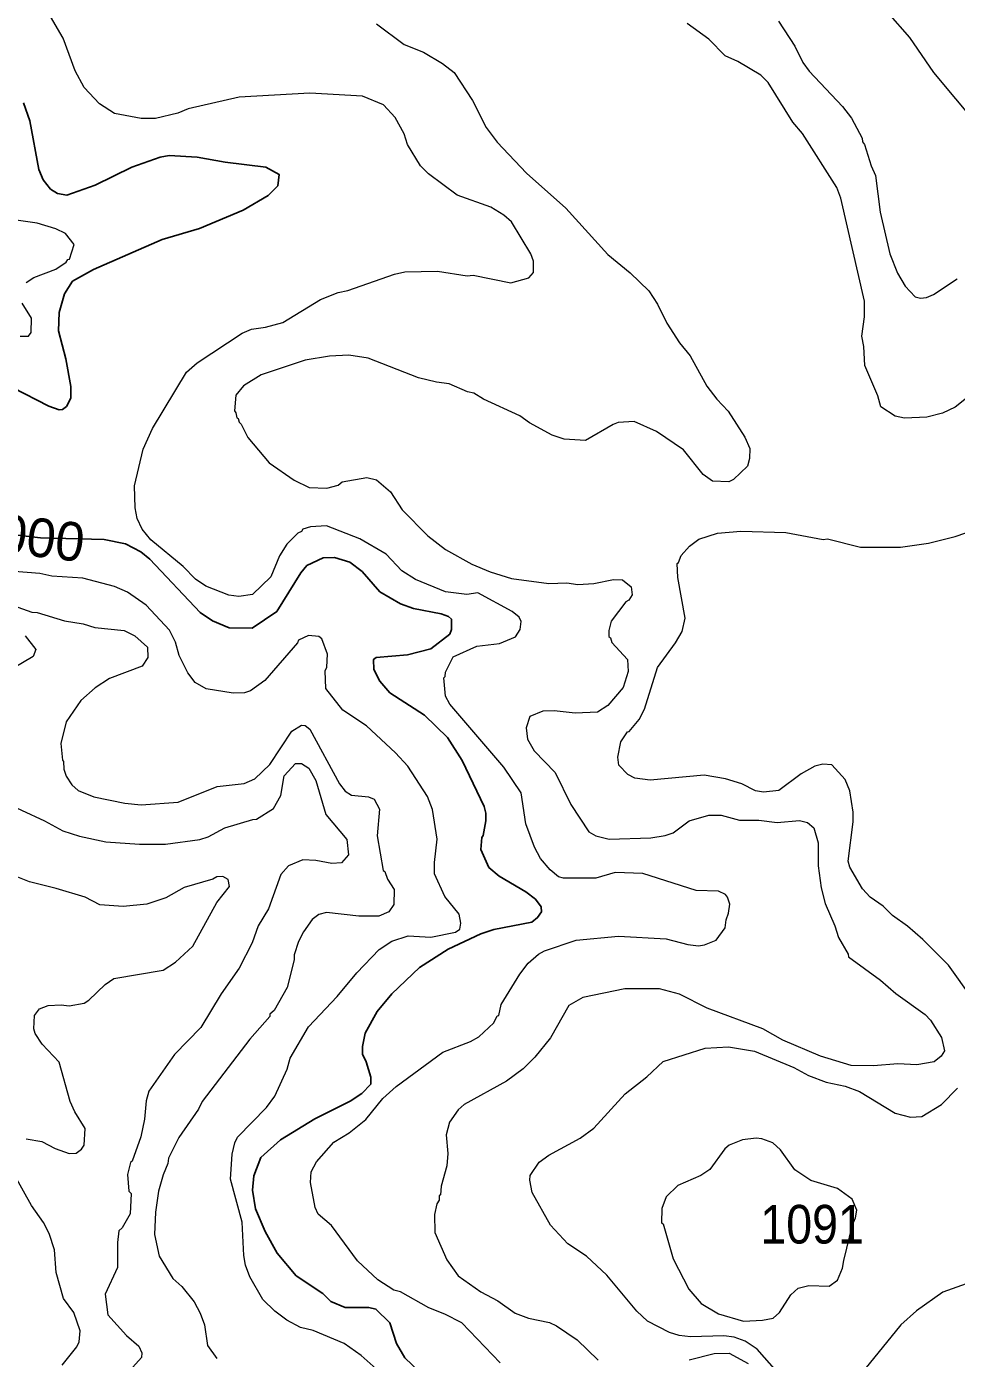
# Model space of a CAD drawing. Extents: x 447.8 to 473.9, y 7733.1 to 7760.8.
# Drawn here: x 462.61 to 464.533, y 7750.473 to 7753.226 of the extents above; entities that cross this region are included whole.
import ezdxf
from ezdxf.enums import TextEntityAlignment as Align

# ---------------------------------------------------------------- set-up
doc = ezdxf.new("R2010")
doc.units = 0
doc.header["$LTSCALE"] = 0.032
doc.layers.add('1', color=7, linetype='Continuous', lineweight=25)
doc.layers.add('2', color=7, linetype='Continuous', lineweight=13)
doc.layers.add('21', color=7, linetype='Continuous')
doc.layers.add('61', color=7, linetype='Continuous')

msp = doc.modelspace()

# ---------------------------------------------------------------- linework, layer by layer
at = {"layer": '1'}
for points in [[(462.5811, 7752.4805), (462.6558, 7752.4414), (462.6776, 7752.434), (462.6846, 7752.4344), (462.6928, 7752.4412), (462.7014, 7752.4584), (462.7016, 7752.482), (462.6913, 7752.5394), (462.676, 7752.5971), (462.6776, 7752.6356), (462.6887, 7752.674), (462.705, 7752.7), (462.7486, 7752.7239), (462.8905, 7752.7865), (462.9676, 7752.8088), (463.0578, 7752.8468), (463.1094, 7752.8769), (463.1295, 7752.8973), (463.1324, 7752.9208), (463.1048, 7752.9356), (463.0206, 7752.9461), (462.9626, 7752.9566), (462.9049, 7752.9597), (462.886, 7752.9565), (462.828, 7752.9355), (462.7521, 7752.8984), (462.6936, 7752.878), (462.6739, 7752.8814), (462.6596, 7752.8904), (462.6442, 7752.9094), (462.6354, 7752.9308), (462.6167, 7753.0315), (462.6037, 7753.069)], [(463.5601, 7751.6002), (463.5562, 7751.6143), (463.5106, 7751.7089), (463.4805, 7751.7568), (463.4329, 7751.8027), (463.3611, 7751.849), (463.3405, 7751.8733), (463.3285, 7751.8969), (463.3277, 7751.9181), (463.3327, 7751.9217), (463.3978, 7751.9274), (463.4458, 7751.9399), (463.4853, 7751.9704), (463.4888, 7751.98), (463.4887, 7752.001), (463.4823, 7752.0066), (463.4671, 7752.012), (463.4099, 7752.0231), (463.3835, 7752.0333), (463.3408, 7752.0579), (463.3043, 7752.0997), (463.2784, 7752.119), (463.2467, 7752.1285), (463.2234, 7752.1278), (463.1897, 7752.1122), (463.1772, 7752.0971), (463.1275, 7752.0171), (463.0766, 7751.9828), (463.0293, 7751.9834), (462.9944, 7751.9977), (462.9688, 7752.0152), (462.8653, 7752.1251), (462.8464, 7752.1407), (462.8148, 7752.1569), (462.7705, 7752.1661), (462.6392, 7752.1696), (462.5912, 7752.1752)], [(463.566, 7751.4879), (463.5498, 7751.5249), (463.5512, 7751.5501), (463.5544, 7751.554), (463.5601, 7751.5843), (463.5601, 7751.6002)], [(463.4227, 7750.4453), (463.3923, 7750.4742), (463.3751, 7750.5035), (463.3613, 7750.5468), (463.3324, 7750.575), (463.318, 7750.5781), (463.2691, 7750.5783), (463.2396, 7750.5903), (463.2226, 7750.6071), (463.1679, 7750.6434), (463.1285, 7750.6905), (463.1037, 7750.7352), (463.0837, 7750.7824), (463.0776, 7750.8208), (463.0802, 7750.8507), (463.0945, 7750.8883), (463.1353, 7750.9245), (463.2065, 7750.9685), (463.279, 7751.0048), (463.3034, 7751.0204), (463.322, 7751.0402), (463.3218, 7751.0543), (463.3123, 7751.0859), (463.3045, 7751.102), (463.3045, 7751.118), (463.3105, 7751.1452), (463.335, 7751.1901), (463.3651, 7751.2265), (463.4225, 7751.2808), (463.4818, 7751.3191), (463.5496, 7751.3504), (463.5762, 7751.3595), (463.6552, 7751.375), (463.6669, 7751.3842), (463.6746, 7751.3965), (463.6745, 7751.4064), (463.6625, 7751.4226), (463.6425, 7751.4377), (463.5871, 7751.4698), (463.566, 7751.4879)]]:
    msp.add_lwpolyline(points, dxfattribs=at)
at = {"layer": '2'}
for points in [[(464.6192, 7752.9723), (464.4864, 7753.1315), (464.4364, 7753.204), (464.392, 7753.255), (464.3576, 7753.3119), (464.3206, 7753.3917), (464.3077, 7753.4247), (464.2879, 7753.4731), (464.2343, 7753.6308), (464.2332, 7753.6641), (464.2311, 7753.6666), (464.2347, 7753.6953), (464.2547, 7753.7318), (464.2762, 7753.7542), (464.3421, 7753.7868), (464.3901, 7753.8066), (464.4936, 7753.8318), (464.5449, 7753.8494)], [(463.2746, 7752.6809), (463.3708, 7752.7146), (463.3926, 7752.7192), (463.4599, 7752.7208), (463.5212, 7752.7108), (463.5339, 7752.7127), (463.6112, 7752.6969), (463.6489, 7752.7072), (463.6586, 7752.7178), (463.6586, 7752.7411), (463.6528, 7752.7567), (463.6131, 7752.8224), (463.5968, 7752.8365), (463.5702, 7752.8533), (463.5007, 7752.8776), (463.4415, 7752.922), (463.425, 7752.9387), (463.3981, 7752.9824), (463.391, 7753.0046), (463.3725, 7753.0383), (463.3485, 7753.0646), (463.3051, 7753.0828), (463.1959, 7753.0889), (463.0495, 7753.0807), (462.944, 7753.056), (462.9229, 7753.0475), (462.8764, 7753.036), (462.8469, 7753.036), (462.7921, 7753.0465), (462.7607, 7753.0667), (462.7294, 7753.1002), (462.7103, 7753.1347), (462.6855, 7753.2021), (462.6597, 7753.247)], [(463.3339, 7753.2318), (463.3908, 7753.1892), (463.431, 7753.1737), (463.4702, 7753.1501), (463.4944, 7753.1313), (463.5322, 7753.0733), (463.5606, 7753.018), (463.583, 7752.9876), (463.644, 7752.9231), (463.725, 7752.851), (463.8121, 7752.7551), (463.8581, 7752.7171), (463.8966, 7752.6802), (463.9149, 7752.6526), (463.9338, 7752.6131), (463.9604, 7752.5723), (463.9827, 7752.5458), (464.0171, 7752.4831), (464.0376, 7752.4559), (464.0609, 7752.431), (464.0956, 7752.3778), (464.106, 7752.3542)], [(464.5541, 7752.4579), (464.5301, 7752.4397), (464.5041, 7752.427), (464.4719, 7752.4187), (464.4255, 7752.4171), (464.4064, 7752.4209), (464.3766, 7752.4403), (464.3704, 7752.463), (464.3436, 7752.5257), (464.3416, 7752.5653), (464.3376, 7752.5863), (464.3426, 7752.6264), (464.3432, 7752.6587), (464.2943, 7752.8715), (464.2855, 7752.894), (464.2149, 7753.0052), (464.1945, 7753.0285), (464.1434, 7753.1107), (464.1283, 7753.1256), (464.0808, 7753.1539), (464.0548, 7753.1658), (464.0213, 7753.2), (463.9763, 7753.2324)], [(464.1651, 7753.2373), (464.199, 7753.1858), (464.2157, 7753.1524), (464.2282, 7753.1339), (464.2974, 7753.061), (464.3158, 7753.0369), (464.3383, 7752.9955), (464.3387, 7752.9884), (464.3432, 7752.9829), (464.3566, 7752.9383), (464.3657, 7752.9185), (464.3754, 7752.8424), (464.3953, 7752.7568)], [(462.6089, 7752.697), (462.6253, 7752.7074), (462.6706, 7752.7245), (462.6918, 7752.7393), (462.6951, 7752.7447), (462.6985, 7752.7453), (462.7087, 7752.7756), (462.6905, 7752.7986), (462.6708, 7752.8085), (462.6318, 7752.8201), (462.5791, 7752.8276)], [(464.3953, 7752.7568), (464.4113, 7752.7163), (464.4268, 7752.6894), (464.4475, 7752.6676), (464.4584, 7752.6648), (464.4711, 7752.6663)], [(463.0752, 7752.6006), (463.104, 7752.6046), (463.1398, 7752.6143), (463.2177, 7752.6618), (463.2547, 7752.6767), (463.2746, 7752.6809)], [(464.4711, 7752.6663), (464.4857, 7752.6727), (464.5346, 7752.7046)], [(462.5971, 7752.5863), (462.6142, 7752.5864), (462.6198, 7752.5942), (462.6199, 7752.6235), (462.601, 7752.6544)], [(463.3368, 7750.6357), (463.2941, 7750.6744), (463.2407, 7750.7478), (463.2129, 7750.771), (463.2071, 7750.7847), (463.1971, 7750.8368), (463.1985, 7750.8589), (463.2095, 7750.8794), (463.2454, 7750.9199), (463.2774, 7750.9392), (463.3119, 7750.9666), (463.3467, 7751.01), (463.3747, 7751.0348), (463.4712, 7751.1064), (463.5279, 7751.1284), (463.5452, 7751.138), (463.5767, 7751.1664), (463.5834, 7751.1815), (463.5865, 7751.1821), (463.5918, 7751.2047), (463.63, 7751.2671), (463.6473, 7751.2898), (463.6689, 7751.3085), (463.6814, 7751.3153), (463.7465, 7751.3373), (463.8343, 7751.3461), (463.9328, 7751.3405), (463.9774, 7751.3286), (463.9999, 7751.3262), (464.0117, 7751.3278), (464.0361, 7751.3375), (464.0546, 7751.3629), (464.0565, 7751.3796), (464.0619, 7751.3935), (464.0642, 7751.412), (464.0596, 7751.4268), (464.0552, 7751.432), (464.0411, 7751.4392), (463.9946, 7751.44), (463.8845, 7751.4754), (463.8271, 7751.4776), (463.7875, 7751.4655), (463.7206, 7751.4658), (463.7104, 7751.4685), (463.6926, 7751.4832), (463.6728, 7751.5066), (463.6602, 7751.53), (463.6424, 7751.5783), (463.6328, 7751.6421), (463.5968, 7751.6951), (463.4852, 7751.8253), (463.4764, 7751.8423), (463.4728, 7751.8797), (463.4759, 7751.8827), (463.4767, 7751.8918), (463.4926, 7751.9236), (463.5409, 7751.9457), (463.5881, 7751.9512), (463.6215, 7751.9649), (463.6311, 7751.9801), (463.633, 7751.9967), (463.6289, 7752.0056), (463.6144, 7752.0172), (463.5431, 7752.0554), (463.5205, 7752.0524), (463.4763, 7752.0579), (463.4146, 7752.0832), (463.3864, 7752.1012), (463.3536, 7752.1355), (463.299, 7752.1672), (463.2304, 7752.1942), (463.1974, 7752.1919), (463.1813, 7752.187), (463.1786, 7752.1824), (463.1707, 7752.179), (463.1484, 7752.156), (463.1334, 7752.1324), (463.115, 7752.089), (463.0772, 7752.052), (463.049, 7752.0484), (463.0284, 7752.0508), (462.9809, 7752.0698), (462.9595, 7752.0839), (462.9338, 7752.1102), (462.867, 7752.1651), (462.8489, 7752.1874), (462.8389, 7752.2091), (462.8348, 7752.2312), (462.8333, 7752.2771), (462.851, 7752.3528), (462.8706, 7752.3953), (462.9405, 7752.5122), (462.9629, 7752.5309), (463.0562, 7752.5927), (463.0752, 7752.6006)], [(464.0288, 7752.2865), (464.0096, 7752.3003), (463.9683, 7752.351), (463.9125, 7752.3892), (463.8665, 7752.4102), (463.8338, 7752.4075), (463.8229, 7752.4037), (463.7658, 7752.3705), (463.7219, 7752.3736), (463.6973, 7752.3818), (463.6498, 7752.4072), (463.6298, 7752.4218), (463.5552, 7752.456), (463.5352, 7752.4683), (463.5218, 7752.471), (463.4837, 7752.4877), (463.4576, 7752.491), (463.4205, 7752.5002), (463.3162, 7752.5407), (463.2762, 7752.5469), (463.2364, 7752.5453), (463.1862, 7752.5366), (463.0954, 7752.5065), (463.0589, 7752.4834), (463.0427, 7752.4641), (463.0399, 7752.4318), (463.0431, 7752.428), (463.0447, 7752.4174), (463.0478, 7752.4161), (463.0495, 7752.4085), (463.0541, 7752.4044), (463.0678, 7752.3765), (463.1118, 7752.3245), (463.1633, 7752.2884), (463.1947, 7752.2737), (463.231, 7752.2719), (463.2547, 7752.2786), (463.2624, 7752.2851), (463.314, 7752.2944), (463.3335, 7752.2895), (463.3627, 7752.2642), (463.3871, 7752.2275), (463.4402, 7752.1738), (463.4761, 7752.145), (463.5307, 7752.1147), (463.5686, 7752.099), (463.613, 7752.085), (463.6901, 7752.0749), (463.7272, 7752.0764), (463.7498, 7752.0732), (463.7834, 7752.0753), (463.8235, 7752.0836), (463.8425, 7752.0829), (463.8607, 7752.068), (463.8623, 7752.0519), (463.8556, 7752.0402), (463.8496, 7752.037), (463.8193, 7751.9972), (463.8142, 7751.9776), (463.8143, 7751.9652), (463.8174, 7751.963), (463.8204, 7751.9527), (463.8529, 7751.9177), (463.8543, 7751.8933), (463.844, 7751.8601), (463.8124, 7751.8229), (463.7908, 7751.8089), (463.7446, 7751.8071), (463.7008, 7751.8118), (463.678, 7751.811), (463.6508, 7751.7998), (463.6432, 7751.7768), (463.6458, 7751.7532), (463.6601, 7751.7288), (463.7035, 7751.6845), (463.7356, 7751.618), (463.7727, 7751.5619), (463.7876, 7751.5534), (463.8147, 7751.5466), (463.9012, 7751.549), (463.9306, 7751.5539), (463.9475, 7751.5598), (463.9804, 7751.5843), (464.021, 7751.5962), (464.0467, 7751.5962), (464.0844, 7751.5859), (464.1243, 7751.5858), (464.1621, 7751.581), (464.2086, 7751.585), (464.2248, 7751.5808), (464.2384, 7751.5699), (464.2472, 7751.539), (464.2473, 7751.4916), (464.2536, 7751.446), (464.2613, 7751.4134)], [(464.106, 7752.3542), (464.1053, 7752.3336), (464.1012, 7752.3173), (464.0722, 7752.2901), (464.0621, 7752.2851), (464.0288, 7752.2865)], [(464.1337, 7751.6436), (464.1173, 7751.6465), (464.0894, 7751.6606), (464.0552, 7751.6712), (464.0111, 7751.6789), (463.8996, 7751.6684), (463.8682, 7751.6722), (463.8536, 7751.68), (463.8349, 7751.6995), (463.8327, 7751.7162), (463.8391, 7751.7477), (463.8525, 7751.7682), (463.8565, 7751.7693), (463.8769, 7751.7937), (463.8879, 7751.815), (463.9149, 7751.901), (463.9523, 7751.9524), (463.9657, 7751.9755), (463.9721, 7752.0034), (463.957, 7752.0873), (463.9554, 7752.1161), (463.9585, 7752.1183), (463.9638, 7752.1331), (463.9807, 7752.1523), (464.0003, 7752.1669), (464.0386, 7752.179), (464.0871, 7752.183), (464.1801, 7752.1806), (464.2577, 7752.1662), (464.2664, 7752.1675), (464.3346, 7752.1502), (464.4175, 7752.15), (464.4751, 7752.1582), (464.5305, 7752.1725), (464.5927, 7752.1932)], [(463.106, 7750.992), (463.1234, 7751.0154), (463.1488, 7751.0709), (463.1555, 7751.0939), (463.1928, 7751.1585), (463.2521, 7751.2209), (463.293, 7751.2698), (463.3395, 7751.318), (463.3656, 7751.3359), (463.399, 7751.3469), (463.4458, 7751.3437), (463.4972, 7751.3539), (463.5063, 7751.3607), (463.508, 7751.373), (463.5044, 7751.3917), (463.4748, 7751.4278), (463.4537, 7751.4746), (463.4536, 7751.4983), (463.459, 7751.5464), (463.4496, 7751.6079), (463.4395, 7751.6346), (463.3987, 7751.6974), (463.3728, 7751.7251), (463.3127, 7751.7804), (463.2638, 7751.8131), (463.2291, 7751.8579), (463.2274, 7751.8941), (463.2308, 7751.9022), (463.2323, 7751.9289), (463.2208, 7751.9604), (463.2147, 7751.9652), (463.1931, 7751.9673), (463.1726, 7751.958), (463.1703, 7751.952), (463.1026, 7751.8746), (463.0729, 7751.8532), (463.0607, 7751.8488), (463.0372, 7751.848), (462.9816, 7751.857), (462.9585, 7751.8701), (462.9434, 7751.8906), (462.9257, 7751.9261), (462.9177, 7751.9536), (462.9054, 7751.9783), (462.8571, 7752.0299), (462.8191, 7752.0573), (462.7919, 7752.0687), (462.7264, 7752.0859), (462.6626, 7752.0901), (462.6375, 7752.0956), (462.585, 7752.0998)], [(462.5452, 7752.0425), (462.6209, 7752.0156), (462.6318, 7752.0153), (462.6885, 7751.9979), (462.7273, 7751.9914), (462.7513, 7751.9839), (462.8122, 7751.9778), (462.8341, 7751.9669), (462.8603, 7751.9437), (462.8611, 7751.9217), (462.8494, 7751.9044), (462.7816, 7751.8783), (462.7516, 7751.8593), (462.7225, 7751.8334), (462.6919, 7751.7891), (462.6809, 7751.7445), (462.6841, 7751.7096), (462.6866, 7751.7068), (462.6874, 7751.691), (462.6917, 7751.6764), (462.7037, 7751.6591), (462.7167, 7751.6472), (462.7494, 7751.634), (462.8134, 7751.6209), (462.8471, 7751.6171), (462.9238, 7751.6226), (463.0041, 7751.6551), (463.0598, 7751.6613), (463.0819, 7751.6714), (463.1134, 7751.701), (463.1589, 7751.7697), (463.1785, 7751.7821), (463.1861, 7751.7812), (463.1955, 7751.7741), (463.2575, 7751.661), (463.2689, 7751.6454), (463.2819, 7751.6376), (463.3169, 7751.634), (463.329, 7751.629), (463.3396, 7751.6087), (463.335, 7751.553), (463.3476, 7751.4814), (463.351, 7751.4797), (463.3568, 7751.4636), (463.3701, 7751.4424), (463.3699, 7751.4117), (463.359, 7751.3961), (463.3383, 7751.3871), (463.2973, 7751.3871), (463.2304, 7751.395), (463.2144, 7751.3904), (463.2006, 7751.3802), (463.1827, 7751.3549), (463.1727, 7751.3351), (463.1635, 7751.3075), (463.1633, 7751.2972), (463.149, 7751.2398), (463.1222, 7751.1922), (463.1134, 7751.1847), (463.1132, 7751.1799), (463.0717, 7751.1327), (462.9733, 7751.0041), (462.9654, 7750.9884), (462.9251, 7750.93), (462.9038, 7750.8871), (462.902, 7750.8757), (462.8922, 7750.8525), (462.8826, 7750.8184), (462.8764, 7750.7753)], [(462.6072, 7751.9671), (462.6294, 7751.9386), (462.624, 7751.9244), (462.5832, 7751.9002)], [(462.9681, 7751.5458), (462.9857, 7751.5515), (463.0203, 7751.5697), (463.078, 7751.5874), (463.0856, 7751.5876), (463.1204, 7751.6096), (463.1359, 7751.6368), (463.1428, 7751.6772), (463.1665, 7751.7029), (463.1785, 7751.7028), (463.1938, 7751.6932), (463.2081, 7751.6679), (463.2288, 7751.5976), (463.2722, 7751.5456), (463.2755, 7751.5141), (463.2611, 7751.4978), (463.2411, 7751.4962), (463.2082, 7751.5024), (463.1811, 7751.504), (463.1519, 7751.491), (463.136, 7751.4733), (463.1103, 7751.4027), (463.0893, 7751.3671), (463.0766, 7751.3322), (463.0497, 7751.2799), (463.0126, 7751.2267), (462.9703, 7751.1574), (462.9162, 7751.1013), (462.8632, 7751.0256), (462.8572, 7751.0054), (462.854, 7750.9674), (462.8466, 7750.9311), (462.8287, 7750.8807), (462.825, 7750.8777), (462.8188, 7750.8534), (462.8218, 7750.8188), (462.8267, 7750.8139), (462.8242, 7750.7719), (462.8075, 7750.7428), (462.8008, 7750.7367), (462.7979, 7750.7129), (462.7978, 7750.6608), (462.7723, 7750.6056), (462.7781, 7750.5628), (462.8164, 7750.5204), (462.8424, 7750.4982), (462.8482, 7750.4847), (462.8477, 7750.475), (462.8299, 7750.4549)], [(464.2756, 7751.7), (464.2567, 7751.7012), (464.2401, 7751.6973), (464.2121, 7751.6814), (464.1659, 7751.6471), (464.1337, 7751.6436)], [(464.5661, 7751.2166), (464.5166, 7751.2858), (464.4638, 7751.3387), (464.432, 7751.3664), (464.401, 7751.3887), (464.3812, 7751.4076), (464.3548, 7751.4262), (464.3387, 7751.4437), (464.3126, 7751.4886), (464.3089, 7751.5008), (464.3193, 7751.5821), (464.3192, 7751.6022), (464.3129, 7751.6464), (464.3027, 7751.6698), (464.2756, 7751.7)], [(462.5513, 7751.6282), (462.6468, 7751.5844), (462.6853, 7751.5635)], [(462.6853, 7751.5635), (462.7194, 7751.5526), (462.7742, 7751.5409), (462.8435, 7751.5362), (462.8976, 7751.5362), (462.9681, 7751.5458)], [(462.6095, 7750.9266), (462.6413, 7750.9217), (462.6694, 7750.9068), (462.6984, 7750.8965), (462.7125, 7750.897), (462.7239, 7750.9053), (462.7293, 7750.914), (462.7309, 7750.9483), (462.7098, 7750.9829), (462.7004, 7751.0044), (462.6775, 7751.0852), (462.6422, 7751.1228), (462.6281, 7751.1446), (462.6248, 7751.1546), (462.6264, 7751.1819), (462.6369, 7751.1959), (462.6548, 7751.2024), (462.6818, 7751.2042), (462.6978, 7751.2019), (462.7294, 7751.2077), (462.7387, 7751.2134), (462.7724, 7751.2462), (462.7907, 7751.2587), (462.8923, 7751.2757), (462.9183, 7751.2923), (462.9536, 7751.3252), (463.0037, 7751.4157), (463.0295, 7751.4485), (463.0269, 7751.4633), (463.0159, 7751.4695), (463.0038, 7751.4687), (462.9954, 7751.4638), (462.936, 7751.4463), (462.898, 7751.4252), (462.8588, 7751.4123), (462.8101, 7751.407), (462.7616, 7751.411), (462.7312, 7751.4262), (462.6712, 7751.4446), (462.616, 7751.4579), (462.5917, 7751.4677)], [(464.2613, 7751.4134), (464.2818, 7751.3672), (464.2889, 7751.3434), (464.3094, 7751.3084), (464.3099, 7751.3034), (464.3759, 7751.2551)], [(464.3759, 7751.2551), (464.4074, 7751.2275), (464.4686, 7751.184), (464.4793, 7751.1725), (464.502, 7751.1361), (464.5084, 7751.1088), (464.5016, 7751.0981), (464.487, 7751.0859), (464.4512, 7751.08), (464.4117, 7751.0817), (464.3615, 7751.0776), (464.3153, 7751.0786), (464.2522, 7751.0975), (464.1737, 7751.1312), (464.1326, 7751.154), (464.0178, 7751.197), (463.9604, 7751.2258), (463.9187, 7751.2372), (463.8476, 7751.2371), (463.7607, 7751.2189), (463.7313, 7751.2029), (463.6933, 7751.1359), (463.6609, 7751.0958), (463.637, 7751.0713), (463.6027, 7751.0462), (463.5147, 7750.9976), (463.5024, 7750.9868), (463.4844, 7750.9613), (463.4776, 7750.9353), (463.4815, 7750.8964), (463.4791, 7750.8708), (463.4673, 7750.8288), (463.4664, 7750.8114), (463.4632, 7750.8089), (463.4631, 7750.7998), (463.4584, 7750.7927), (463.4536, 7750.7702), (463.4544, 7750.733), (463.4793, 7750.6766), (463.5029, 7750.6437), (463.5493, 7750.6103), (463.5847, 7750.592), (463.6205, 7750.5668), (463.6482, 7750.5565), (463.6913, 7750.5473), (463.7062, 7750.5405), (463.7488, 7750.5115), (463.7924, 7750.4695)], [(464.1614, 7750.4458), (464.121, 7750.4918), (464.0961, 7750.5087), (464.0736, 7750.5166), (464.0519, 7750.5197), (463.983, 7750.5174), (463.9599, 7750.5201), (463.9394, 7750.5264), (463.8939, 7750.5499), (463.8722, 7750.5708), (463.8097, 7750.6453), (463.768, 7750.6846), (463.7297, 7750.7097), (463.6937, 7750.7483), (463.6557, 7750.8161), (463.6507, 7750.8414), (463.6514, 7750.8512), (463.6701, 7750.8789), (463.6898, 7750.8934), (463.7549, 7750.9285), (463.7832, 7750.9489), (463.8477, 7751.0197), (463.8926, 7751.0549), (463.9263, 7751.087), (464.0131, 7751.1145), (464.0618, 7751.1169), (464.1153, 7751.1082), (464.1971, 7751.0745), (464.2269, 7751.0581), (464.2637, 7751.0443), (464.3026, 7751.0361), (464.3323, 7751.0246), (464.4061, 7750.9797), (464.4383, 7750.9719), (464.4616, 7750.9734), (464.5023, 7750.9977), (464.5354, 7751.0317)], [(463.0558, 7750.7545), (463.032, 7750.8432), (463.0352, 7750.8952), (463.0407, 7750.9186), (463.0463, 7750.9301), (463.106, 7750.992)], [(462.6834, 7750.4587), (462.7141, 7750.4968), (462.719, 7750.5069), (462.7211, 7750.5302), (462.7079, 7750.5677), (462.6864, 7750.597), (462.6711, 7750.6507), (462.6678, 7750.6975), (462.6567, 7750.7313), (462.6452, 7750.7541), (462.6205, 7750.7889), (462.5636, 7750.8907)], [(462.8764, 7750.7753), (462.8748, 7750.7294), (462.8846, 7750.6845), (462.9124, 7750.6384), (462.9309, 7750.6217), (462.9567, 7750.5899)], [(463.3639, 7750.424), (463.3017, 7750.4787), (463.2666, 7750.5041), (463.2025, 7750.5306), (463.1764, 7750.5372), (463.1486, 7750.5518), (463.1235, 7750.5708), (463.0987, 7750.5948), (463.072, 7750.6416), (463.0627, 7750.6658), (463.0592, 7750.6857), (463.0558, 7750.7545)], [(465.0792, 7750.4528), (465.0888, 7750.52), (465.1095, 7750.5979), (465.1129, 7750.6222), (465.1049, 7750.6444), (465.1015, 7750.6781), (465.0929, 7750.6957), (465.0735, 7750.7065), (465.0654, 7750.7073), (465.0307, 7750.7007), (465.0089, 7750.6906), (464.915, 7750.6268), (464.8505, 7750.5969), (464.8047, 7750.5846), (464.7822, 7750.5847), (464.737, 7750.5969), (464.6826, 7750.627), (464.6581, 7750.6376), (464.6014, 7750.6375), (464.563, 7750.6303), (464.5047, 7750.6099), (464.4507, 7750.571), (464.4183, 7750.5426), (464.3347, 7750.4398)], [(463.5102, 7750.5463), (463.475, 7750.5643), (463.4418, 7750.5773), (463.383, 7750.6103), (463.3693, 7750.614), (463.3368, 7750.6357)], [(462.9567, 7750.5899), (462.9692, 7750.5665), (462.9777, 7750.5426), (462.9844, 7750.4995), (463.0033, 7750.4725)], [(463.5898, 7750.4637), (463.5102, 7750.5463)], [(463.9806, 7750.4699), (464.0322, 7750.4828), (464.0632, 7750.4836), (464.1026, 7750.4627)]]:
    msp.add_lwpolyline(points, dxfattribs=at)
msp.add_lwpolyline([(464.1695, 7750.9042), (464.1535, 7750.9184), (464.1308, 7750.9269), (464.119, 7750.9282), (464.0907, 7750.9247), (464.0633, 7750.9136), (464.0539, 7750.906), (464.023, 7750.8635), (464.0041, 7750.851), (463.9572, 7750.8301), (463.9328, 7750.8072), (463.9241, 7750.7826), (463.9233, 7750.7533), (463.9264, 7750.7515), (463.9471, 7750.6791), (463.9793, 7750.616), (464.0053, 7750.5868), (464.0407, 7750.5652), (464.0929, 7750.5502), (464.1323, 7750.5518), (464.154, 7750.5565), (464.1668, 7750.5678), (464.1907, 7750.6045), (464.2057, 7750.6183), (464.2275, 7750.6239), (464.2696, 7750.6225), (464.2872, 7750.6347), (464.2973, 7750.6592), (464.3, 7750.6757), (464.3183, 7750.7489), (464.3242, 7750.7638), (464.3272, 7750.7791), (464.3177, 7750.8024), (464.2871, 7750.8243), (464.2317, 7750.8409), (464.1985, 7750.8626)], close=True, dxfattribs=at)

# ---------------------------------------------------------------- texts
at = {"layer": '21', "width": 0.9}
msp.add_text('1091', height=0.08, dxfattribs=at).set_placement((464.1275, 7750.7104))
at = {"layer": '61'}
msp.add_text('1000', height=0.08, rotation=353.083, dxfattribs=at).set_placement((462.6063, 7752.1333), align=Align.CENTER)

doc.saveas('drawing.dxf')
